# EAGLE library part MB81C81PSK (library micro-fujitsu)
MICROCONTROLLER/MEMORY DEVICE
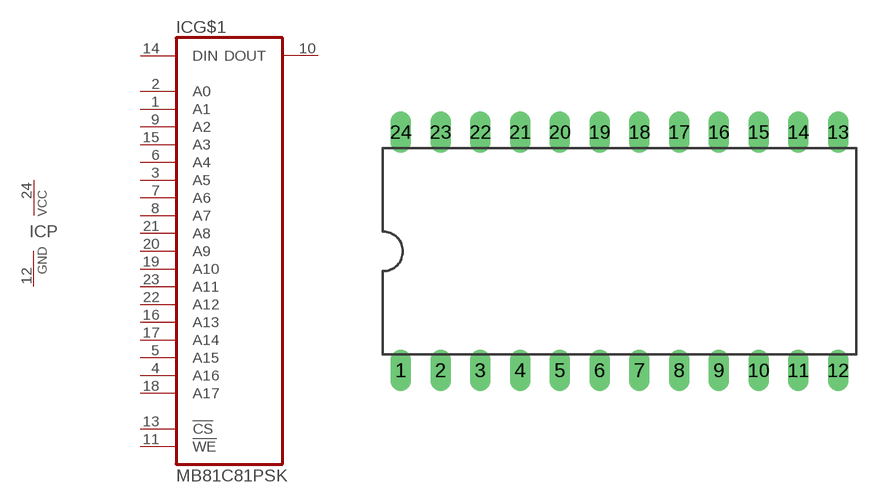
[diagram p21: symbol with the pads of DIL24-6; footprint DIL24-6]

Designator prefix IC; gates G$1=MB81C81 P=VCC-GND

## MB81C81PSK (OC_FARNELL: unknown; OC_NEWARK: unknown)  [DIL24-6]
1  G$1:A1  in
2  G$1:A0  in
3  G$1:A5  in
4  G$1:A16  in
5  G$1:A15  in
6  G$1:A4  in
7  G$1:A6  in
8  G$1:A7  in
9  G$1:A2  in
10  G$1:DOUT  out
11  G$1:!WE  in
12  P:GND  pwr
13  G$1:!CS  in
14  G$1:DIN  in
15  G$1:A3  in
16  G$1:A13  in
17  G$1:A14  in
18  G$1:A17  in
19  G$1:A10  in
20  G$1:A9  in
21  G$1:A8  in
22  G$1:A12  in
23  G$1:A11  in
24  P:VCC  pwr

## Footprint DIL24-6 (pad centres in mm)
Dual In Line Package 0.6 inch
drill 0.813 long: 1 -13.97,-7.62; 2 -11.43,-7.62; 3 -8.89,-7.62; 4 -6.35,-7.62; 5 -3.81,-7.62; 6 -1.27,-7.62; 7 1.27,-7.62; 8 3.81,-7.62; 9 6.35,-7.62; 10 8.89,-7.62; 11 11.43,-7.62; 12 13.97,-7.62; 13 13.97,7.62; 14 11.43,7.62; 15 8.89,7.62; 16 6.35,7.62; 17 3.81,7.62; 18 1.27,7.62; 19 -1.27,7.62; 20 -3.81,7.62; 21 -6.35,7.62; 22 -8.89,7.62; 23 -11.43,7.62; 24 -13.97,7.62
